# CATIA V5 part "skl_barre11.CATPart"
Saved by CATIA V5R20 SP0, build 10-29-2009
Part number: skl_barre11
Publications: "Barre_111", "Barre_112", "Axe_Pivot_b11b10", "Axe_Pivot_b11b7", "Axe_Pivot_b11b2"
Bounding box of the stored display mesh (mm): x -159.748 to 159.748, y -58.143 to 58.143, z 0 to 20
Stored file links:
  C:\Users\Matthieu\Desktop\IFMA\Cours 2A\Thinkmotion\skl_barre11.CATPart
  C:\Users\Matthieu\Desktop\IFMA\Cours 2A\Thinkmotion\skl_IAO_bis.CATProduct
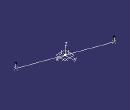
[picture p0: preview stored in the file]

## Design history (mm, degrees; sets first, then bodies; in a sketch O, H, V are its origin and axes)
AxisSystem1: origin (0, 0, 0), X (1, 0, 0), Y (0, 1, 0), Z (0, 0, 1)
Set1
  Point1 "Point.K": linked copy from another document
  Point2 "Point.A": linked copy from another document
  Point3 "Point.C": linked copy from another document
  Plane1 "Plan_Ref": linked copy from another document
Body1 (main body)
  Line1 "Barre_111": type PtPt, FirstPoint Point1, SecondPoint Point2
  Line2 "Barre_112": type PtPt, FirstPoint Point2, SecondPoint Point3
  Line3 "Axe_Pivot_b11b10": type Normal, RefPoint Point1, RefSkin Plane1, Start 0, End 20
  Line4 "Axe_Pivot_b11b7": type Normal, RefPoint Point2, RefSkin Plane1, Start 0, End 20
  Line5 "Axe_Pivot_b11b2": type Normal, RefPoint Point3, RefSkin Plane1, Start 0, End 20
